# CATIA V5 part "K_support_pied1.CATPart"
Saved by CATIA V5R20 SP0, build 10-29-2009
Part number: support_pied2
Bounding box of the stored display mesh (mm): x -30 to 230, y -35 to 35, z -30 to 500
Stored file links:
  G:\Khaled_CFAO_2011\ST2M\ST2M_GR1\lpierredon\Khaled\CAD_thinkMOTION\K_support_pied1.CATPart
  F:\CFAO\Product1.CATProduct
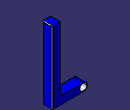
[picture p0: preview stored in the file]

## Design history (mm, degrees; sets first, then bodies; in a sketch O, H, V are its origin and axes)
Set1
  Line1: linked copy from another document
  Line2 "longueur_support": linked copy from another document
  Plane1: linked copy from another document
Body1 (main body)
  Sketch1 on zx-plane, origin (0, 0, 0), H (-1, 0, 0), V (0, 0, 1)
    arc A1 centre (0, 0) radius 30 from (0, -30) to (0, 30) ccw
    circle A2 centre (0, 0) radius 25
    line L1 (0, 30) -> (-170, 30)
    line L2 (-170, 30) -> (-170, 500)
    line L3 (-170, 500) -> (-230, 500)
    line L4 (-230, 500) -> (-230, -30)
    line L5 (-230, -30) -> (0, -30)
    reference projected line E1 (-200, 0) -> (0, 0) from Line1
    reference projected line E2 (-200, 0) -> (-200, 500) from Line2
    reference intersected line E3 through (0, 500) direction (-1, 0) from Plane1
    radius A1 = 30
    distance A2 A1 = 5
    distance L2 L4 = 60
    horizontal: L1 H, L3 H, L5 H
    vertical: L2 V, L4 V
    tangency: L5 A1
    symmetry: L1 L5 E1, L2 L4 E2
    coincidence: L3 E3
  Pad1: profile Sketch1, direction (0, 1, 0), length 35, mirrored extent
  Fillet1: radius 5, on face of Pad1 from Sketch1.L4
  Fillet2: radius 1, on end face of Pad1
